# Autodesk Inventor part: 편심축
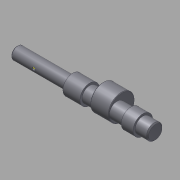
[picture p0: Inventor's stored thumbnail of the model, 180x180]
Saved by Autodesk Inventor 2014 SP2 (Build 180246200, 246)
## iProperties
Company: 한국ATC센터
Created: 2015-12
Part Number: 편심축
Document SubType Name: Modeling
Designer: mdu
Density: 7.86 g/cm^3
Mass: 225.292 g
Surface Area: 81.2409 cm^2
Volume: 28.6631 cm^3
Material: 강철, 연강
Appearance: 강철
Author: mdu
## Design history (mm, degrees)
sketch "스케치1"
  geometry: L1 (-86, 0)-(86, 0); L2 (-86, 0)-(-86, 6); L3 (-86, 6)-(-32, 6); L4 (-32, 6)-(-32, 9.5); L5 (-32, 9.5)-(-15.5, 9.5); L6 (-15.5, 9.5)-(-15.5, 7.5); L7 (-15.5, 7.5)-(48, 7.5); L8 (86, 6)-(86, 0); L9 (36, 7.5)-(36, 9.5); L10 (36, 9.5)-(24.5, 9.5); L11 (24.5, 9.5)-(24.5, 7.5); L12 (48, 7.5)-(48, 6); L13 (48, 6)-(86, 6); 2 further points
  constraints: 26 end point, 6 parallel, 6 perpendicular, 2 point on line, 1 coincident, 1 horizontal, 1 midpoint
  dimensions: "d1" = 12 diameter of L3 L1; "d2" = 15 diameter of L7 L1; "d4" = 16.5 distance of L4.end L5.end; "d5" = 19 diameter of L5 L1; "d24" = 11.5 distance of L9.end L10.end; "d25" = 19 diameter of L10 L1; "d27" = 40 distance between parallel lines of L11 L6; "d28" = 54 distance of L2.end L3.end; "d29" = 50 distance between parallel lines of L8 L9; "d41" = 38 distance between parallel lines of L8 L12; "d42" = 12 diameter of L13 L1
revolve "회전1" stored, may be unused: angle "d6" = 90 deg
node "작업 평면1"
sketch "스케치2"
  geometry: C1 r 7.5 at (0, 0) reference; C2 r 12.5 at (0, 4.5); 1 further point
  constraints: 1 centre point, 1 vertical alignment
  dimensions: "d8" = 4.5 distance of point (0, 0) C2.centre; "d9" = 25 diameter of C2
extrude "돌출1" join sketch "스케치2" distance "d10" = 18; taper "d11" = 0 deg
chamfer "모따기1" distance "d12" = 1; stored, may be unused: second distance "d13" = 2, angle "d14" = 45 deg
chamfer "모따기2" distance "d15" = 0.5; stored, may be unused: second distance "d16" = 2, angle "d17" = 45 deg
node "작업 평면2"
sketch "스케치3"
  geometry: L1 (4, -2)-(18, -2); L2 (18, 2)-(4, 2); L3 (27, 5)-(27, -5) reference; A1 r 2 centre (18, 0) between (18, -2) and (18, 2); A2 r 2 centre (4, 0) between (4, 2) and (4, -2); 2 further points
  constraints: 4 end point, 4 point on circle, 4 tangent, 2 centre point, 1 horizontal, 1 horizontal alignment, 1 midpoint, 1 parallel
  dimensions: "d18" = 7 distance edge to line of A1 L3; "d19" = 4 distance between parallel lines of L2 L1; "d20" = 18 dimension on A1 A2
extrude "돌출2" cut sketch "스케치3" distance "d21" = 2.5; taper "d22" = 0 deg
revolve "회전2" stored, may be unused: angle "d26" = 90 deg
node "작업 평면3"
sketch "스케치4"
  geometry: L1 (44, 5)-(44, -5) reference; 2 further points
  constraints: 1 horizontal alignment
  dimensions: "d30" = 12 distance from line of point (32, 0) L1
hole "구멍1" sketch "스케치4" at (32, 0) diameter "d31" = 6; stored, may be unused: countersink angle "d35" = 90 deg, drill point angle "d37" = 118 deg; dims "d32" = 6, "d33" = 14, "d34" = 3, "d36" = 8
node "작업 평면4"
sketch "스케치5"
  geometry: C1 r 3 at (32, 0) reference; C2 r 8 at (32, 0); 2 further points
  constraints: 1 centre point, 1 coincident, 1 other
  dimensions: "d38" = 16 diameter of C2
extrude "돌출3" cut sketch "스케치5" distance "d39" = 3; taper "d40" = 0 deg
sketch "스케치6"
  geometry: L1 (-85, -6)-(-32, -6) reference; L2 (-86, -5)-(-86, 5) reference; L3 (-85, 6)-(-32, 6) reference; L4 (-64, 6)-(-64, -6); L5 (-64, -6)-(-62.5, -6); L6 (-64, -4.5)-(-62.5, -6); L7 (-64, -6)-(-64, -4.5); 2 further points
  constraints: 8 end point, 4 point on line, 2 perpendicular, 1 coincident
  dimensions: "d43" = 22 distance between parallel lines of L4 L2; "d44" = 45 deg angle of L6 L7; "d45" = 3 diameter of L5.end L4
revolve "회전3" stored, may be unused: angle "d46" = 90 deg
node "작업점1"
chamfer "모따기3" distance "d47" = 0.5; stored, may be unused: second distance "d48" = 2, angle "d49" = 45 deg
sketch "스케치7"
  geometry: C1 r 7.5 at (0, 0) reference; 1 further point
extrude "돌출4" cut sketch "스케치7" stored distance "d50" = 10; taper "d51" = 0 deg
chamfer "모따기4" distance "d52" = 1; stored, may be unused: second distance "d53" = 2, angle "d54" = 45 deg
node "작업 평면5"
node "솔리드1"
node "투영된 루프1"
other parameters: "d7" = 8.5
